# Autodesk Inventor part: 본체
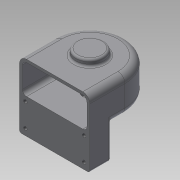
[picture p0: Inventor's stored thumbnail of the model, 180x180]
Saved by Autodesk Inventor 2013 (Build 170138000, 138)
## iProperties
Created: 2015-02
Part Number: 본체
Material: 일반
Document SubType Name: Modeling
Designer: Administrator
Density: 1 g/cm^3
Author: Administrator
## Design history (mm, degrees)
sketch "스케치1"
  geometry: L1 (-50, 0)-(-50, -50); L2 (-50, -50)-(50, -50); L3 (50, -50)-(50, 0); A1 r 50 centre (0, 0) between (50, 0) and (-50, 0); 1 further point
  constraints: 6 end point, 2 point on circle, 2 tangent, 2 vertical, 1 centre point, 1 coincident, 1 perpendicular
  dimensions: "d0" = 50 radius of A1; "d1" = 50 distance from line of L2 point (0, 0)
extrude "돌출1" new body sketch "스케치1" distance "d2" = 50; taper "d3" = 0 deg
fillet "모깎기1" dims "d9" = 10
feature "쉘1" dims "d10" = 4
node "작업 평면1"
sketch "스케치3"
  geometry: L1 (-50, 0)-(-50, -50) reference; L2 (-40, -50)-(-50, -50) reference; L3 (-40, -50)-(40, -50) reference; L4 (50, -50)-(40, -50) reference; L5 (50, -50)-(50, 0) reference; L6 (-50, -20)-(-34.641, -20); L7 (34.641, -20)-(50, -20); A1 r 40 centre (0, 0) between (-34.641, -20) and (34.641, -20); 1 further point
  constraints: 4 end point, 2 perpendicular, 2 point on circle, 2 point on line, 1 centre point, 1 coincident
  dimensions: "d12" = 40 radius of A1; "d13" = 30 distance between parallel lines of L2 L6; "d14" = 30 distance between parallel lines of L4 L7
extrude "돌출2" join sketch "스케치3" stored distance "d15" = 45; taper "d16" = 0 deg
sketch "스케치4"
  geometry: C1 r 25 at (0, 0); A1 r 40 centre (0, 0) between (-34.641, -20) and (34.641, -20) reference
  constraints: 1 centre point, 1 coincident
  dimensions: "d17" = 50 diameter of C1
extrude "돌출3" join sketch "스케치4" distance "d19" = 10; taper "d20" = 0 deg
sketch "스케치5"
  geometry: C1 r 20 at (0, 0); A1 r 40 centre (0, 0) between (40, 0) and (-40, 0) reference
  constraints: 1 centre point, 1 coincident
  dimensions: "d21" = 40 diameter of C1
extrude "돌출4" join sketch "스케치5" distance "d23" = 9; taper "d24" = 0 deg
hole "구멍1" diameter "d27" = 20; stored, may be unused: countersink angle "d31" = 90 deg, drill point angle "d33" = 0 deg; dims "d25" = 10, "d26" = 10, "d28" = 6, "d29" = 28, "d30" = 10, "d32" = 8
hole "구멍2" diameter "d36" = 20; stored, may be unused: countersink angle "d40" = 90 deg, drill point angle "d42" = 0 deg; dims "d34" = 10, "d35" = 10, "d37" = 6, "d38" = 28, "d39" = 8, "d41" = 2
sketch "스케치6"
  geometry: C1 r 14 at (0, 0) reference; 1 further point
  constraints: 1 vertical alignment
  dimensions: "d43" = 18 distance of C1.centre point (0, 18)
hole "구멍3" sketch "스케치6" at (0, 18) diameter "d44" = 2.459; stored, may be unused: countersink angle "d48" = 90 deg, drill point angle "d50" = 118 deg; dims "d45" = 6, "d46" = 4, "d47" = 2, "d49" = 9
fillet "모깎기2" dims "d54" = 0.3
chamfer "모따기1" distance "d55" = 10; stored, may be unused: second distance "d56" = 2, angle "d57" = 20 deg
chamfer "모따기2" distance "d58" = 1; stored, may be unused: second distance "d59" = 2, angle "d60" = 20 deg
node "작업 평면2"
sketch "스케치7"
  geometry: L1 (-40, 50)-(40, 50) reference; 2 further points
  constraints: 1 vertical alignment, 1 other
  dimensions: "d61" = 25 distance from line of point (0, 25) L1
feature "엠보싱1" sketch "스케치7" dims "d62" = 0.5, "d63" = 0
sketch "스케치8"
  geometry: L1 (90, -95)-(-10, -95) reference; L2 (-1.75, -86)-(81.75, -86); L3 (81.75, -86)-(81.75, -53); L4 (81.75, -53)-(-1.75, -53); L5 (-1.75, -53)-(-1.75, -86); L6 (-1.75, -86)-(81.75, -53); L7 (81.75, -86)-(-1.75, -53); 7 further points
  constraints: 12 end point, 4 coincident, 3 midpoint, 2 parallel, 1 horizontal, 1 perpendicular, 1 vertical alignment
  dimensions: "d64" = 83.5 distance of L3.end L4.end; "d66" = 33 distance of L2.end L3.end; "d67" = 9 distance between parallel lines of L1 L2
hole "구멍4" sketch "스케치8" at (-1.75, -53), (-1.75, -86), (81.75, -86), (81.75, -53) diameter "d68" = 5.134; stored, may be unused: countersink angle "d72" = 90 deg, drill point angle "d74" = 118 deg; dims "d69" = 10, "d70" = 4, "d71" = 2, "d73" = 13
fillet "모깎기3" dims "d75" = 3
node "솔리드1"
pattern_circular "원형 패턴1" dims angle "d52" = 360 deg
other parameters: "d11" = 45
